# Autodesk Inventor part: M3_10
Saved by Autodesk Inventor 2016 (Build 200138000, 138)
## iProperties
Created: 2015-11
Part Number: M3_10
Material: Generic
Document SubType Name: Modeling
Designer: John
Density: 1 g/cm^3
Appearance: Default
Author: John
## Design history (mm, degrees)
feature "Base1"
body "Solid1"
